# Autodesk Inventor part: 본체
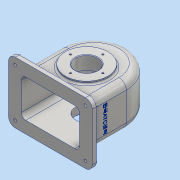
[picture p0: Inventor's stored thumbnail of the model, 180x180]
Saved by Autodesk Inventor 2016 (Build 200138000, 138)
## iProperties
Created: 2018-11
Part Number: 본체
Material: 알루미늄 6061
Document SubType Name: Modeling
Designer: 공506_39
Density: 2.7 g/cm^3
Appearance: 알루미늄 - 평지
Mass: 1092.08 g
Surface Area: 1182.21 cm^2
Volume: 404.475 cm^3
Author: 공506_39
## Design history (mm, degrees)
sketch "스케치2"
  geometry: L1 (-58, 0)-(58, 0); L2 (58, 0)-(58, -78); L3 (58, -78)-(-58, -78); L4 (-58, -78)-(-58, 0); A1 r 58 centre (0, 0) between (58, 0) and (-58, 0); 1 further point
  constraints: 8 end point, 2 parallel, 2 point on circle, 2 tangent, 1 centre point, 1 coincident, 1 horizontal, 1 perpendicular
  dimensions: "d0" = 116 diameter of A1; "d1" = 78 distance between parallel lines of L1 L3
extrude "돌출1" new body sketch "스케치2" distance "d2" = 77; taper "d3" = 0 deg
fillet "모깎기1" dims "d4" = 13
sketch "스케치3"
  geometry: L1 (103, -13)-(103, -64) reference; L2 (90, 0)-(0, 0) reference; L3 (-13, -13)-(-13, -64) reference; L4 (90, -77)-(0, -77) reference; L5 (-30, 16.5)-(120, 16.5); L6 (120, 16.5)-(120, -93.5); L7 (120, -93.5)-(-30, -93.5); L8 (-30, -93.5)-(-30, 16.5); L9 (-30, 16.5)-(120, -93.5); L10 (120, 16.5)-(-30, -93.5); A1 r 13 centre (90, -64) between (90, -77) and (103, -64) reference; A2 r 13 centre (90, -13) between (103, -13) and (90, 0) reference; A3 r 13 centre (0, -13) between (0, 0) and (-13, -13) reference; A4 r 13 centre (0, -64) between (-13, -64) and (0, -77) reference; 6 further points
  constraints: 12 end point, 6 midpoint, 2 parallel, 1 horizontal, 1 horizontal alignment, 1 perpendicular, 1 vertical alignment
  dimensions: "d6" = 110 distance of L5.end L6.end; "d7" = 150 distance of L6.end L7.end
extrude "돌출2" join sketch "스케치3" distance "d8" = 10; taper "d9" = 0 deg
fillet "모깎기2" dims "d10" = 12
node "작업 평면1"
sketch "스케치4"
  geometry: L1 (5, -80.5)-(121, -80.5) reference; L2 (5, -29.5)-(5, -80.5) reference; L3 (121, -29.5)-(5, -29.5) reference; L4 (121, -29.5)-(121, -80.5) reference; L5 (0, 0)-(126, 0) reference; L6 (138, -12)-(138, -98) reference; C1 r 6 at (63, -55); 1 further point
  constraints: 1 centre point
  dimensions: "d12" = 55 distance from line of L5 C1.centre; "d13" = 75 distance from line of L6 C1.centre; "d14" = 12 diameter of C1
extrude "돌출3" join sketch "스케치4" stored distance "d15" = 10; taper "d16" = 5 deg
sketch "스케치5"
  geometry: L1 (-63, -78)-(63, -78) reference; C1 r 38 at (0, -13); 1 further point
  constraints: 1 centre point, 1 vertical alignment
  dimensions: "d17" = 76 diameter of C1; "d18" = 65 distance from line of L1 C1.centre
extrude "돌출4" join sketch "스케치5" distance "d19" = 5; taper "d20" = 0 deg
node "작업 평면2"
node "작업 평면3"
sketch "스케치11"
  geometry: L1 (108, 93.5)-(-18, 93.5) reference; L2 (-30, 81.5)-(-30, -4.5) reference; L3 (-18, -16.5)-(108, -16.5) reference; L4 (120, -4.5)-(120, 81.5) reference; L5 (103, 13)-(103, 64) reference; L6 (0, 0)-(90, 0) reference; L7 (-13, 64)-(-13, 13) reference; L8 (90, 77)-(0, 77) reference; A1 r 12 centre (108, 81.5) between (120, 81.5) and (108, 93.5) reference; A2 r 12 centre (-18, 81.5) between (-18, 93.5) and (-30, 81.5) reference; A3 r 12 centre (-18, -4.5) between (-30, -4.5) and (-18, -16.5) reference; A4 r 12 centre (108, -4.5) between (108, -16.5) and (120, -4.5) reference; A5 r 13 centre (90, 13) between (90, 0) and (103, 13) reference; A6 r 13 centre (0, 13) between (-13, 13) and (0, 0) reference; A7 r 13 centre (0, 64) between (0, 77) and (-13, 64) reference; A8 r 13 centre (90, 64) between (103, 64) and (90, 77) reference; 5 further points
  constraints: 4 coincident
hole "구멍1" sketch "스케치11" at (-18, -4.5), (-18, 81.5), (108, 81.5), (108, -4.5) diameter "d35" = 5; stored, may be unused: countersink angle "d39" = 90 deg, drill point angle "d41" = 118 deg; dims "d36" = 6, "d37" = 12, "d38" = 4, "d40" = 8
node "작업 평면4"
hole "구멍4" diameter "d66" = 4.459; stored, may be unused: countersink angle "d70" = 90 deg, drill point angle "d72" = 118 deg; dims "d64" = 10, "d65" = 10, "d67" = 20, "d68" = 12, "d69" = 4, "d71" = 12.8
fillet "모깎기3" dims "d73" = 3
node "작업 평면5"
sketch "스케치16"
  geometry: L1 (58, 0)-(58, -65) reference; L2 (-58, -65)-(-58, 0) reference; L3 (0, 0)-(0, -121); L4 (-52, 0)-(-52, -121); L5 (52, -121)-(52, 0); A1 r 58 centre (0, 0) between (58, 0) and (-58, 0) reference; A2 r 52 centre (0, 0) between (52, 0) and (-52, 0); A3 r 52 centre (0, -121) between (-52, -121) and (52, -121); 2 further points
  constraints: 8 end point, 4 point on circle, 4 tangent, 2 centre point, 1 midpoint, 1 parallel, 1 vertical
  dimensions: "d74" = 6 radial gap between concentric circles of A1 A2; "d75" = 121 distance of L3.start L3.end
extrude "돌출8" cut sketch "스케치16" stored distance "d76" = 67; taper "d77" = 0 deg
node "작업 평면6"
sketch "스케치17"
  geometry: C1 r 38 at (0, 0) reference; C2 r 28 at (0, 0); 1 further point
  constraints: 1 centre point, 1 coincident
  dimensions: "d79" = 56 diameter of C2
extrude "돌출9" join sketch "스케치17" stored distance "d80" = 67; taper "d81" = 40 deg
sketch "스케치19"
  geometry: L1 (0, 0)-(0, 29); C1 r 38 at (0, 0) reference; 2 further points
  constraints: 2 end point, 1 coincident, 1 point on line, 1 vertical
  dimensions: "d82" = 29 distance of L1.start L1.end
hole "구멍5" sketch "스케치19" at (0, 29) diameter "d83" = 3.242; stored, may be unused: countersink angle "d87" = 90 deg, drill point angle "d89" = 118 deg; dims "d84" = 8, "d85" = 12, "d86" = 4, "d88" = 10
sketch "스케치20"
  geometry: C1 r 38 at (0, -13) reference; C2 r 38 at (0, -13); 1 further point
  constraints: 1 centre point, 1 coincident
  dimensions: "d94" = 76 diameter of C2
extrude "돌출10" join sketch "스케치20" stored distance "d95" = 67; taper "d96" = 0 deg
sketch "스케치21"
  geometry: L1 (0, 0)-(0, 29); C1 r 38 at (0, 0) reference; 2 further points
  constraints: 2 end point, 1 coincident, 1 vertical
  dimensions: "d97" = 29 distance of L1.start L1.end
hole "구멍6" sketch "스케치21" at (0, 29) diameter "d98" = 3.242; stored, may be unused: countersink angle "d102" = 90 deg, drill point angle "d104" = 118 deg; dims "d99" = 8, "d100" = 12, "d101" = 4, "d103" = 10
sketch "스케치22"
  geometry: C1 r 1.621 at (29, 0) reference; C2 r 1.621 at (0, -29) reference; C3 r 1.621 at (-29, 0) reference; C4 r 1.621 at (0, 29) reference; C5 r 38 at (0, 0) reference; 2 further points
  constraints: 1 coincident
hole "구멍7" sketch "스케치22" at (0, 0) diameter "d108" = 40; stored, may be unused: countersink angle "d112" = 90 deg, drill point angle "d114" = 118 deg; dims "d109" = 8, "d110" = 12, "d111" = 4, "d113" = 10
chamfer "모따기2" distance "d115" = 1; stored, may be unused: second distance "d116" = 2, angle "d117" = 45 deg
fillet "모깎기4" dims "d118" = 3
fillet "모깎기5" dims "d119" = 8
fillet "모깎기6" dims "d120" = 3
sketch "스케치23"
  geometry: L1 (-17.5, -78)-(68.5, -78) reference; L2 (80.5, -78)-(80.5, -71) reference; L3 (-29.5, -71)-(-29.5, -78) reference; L4 (-13, 0)-(-13, -65) reference; 2 further points
  constraints: 1 coincident, 1 other
  dimensions: "d123" = 40 distance from line of L1 point (25.5, -38); "d125" = 38.5 distance from line of point (25.5, -38) L4
feature "엠보싱1" sketch "스케치23" dims "d126" = 0.5, "d127" = 0
node "솔리드1"
pattern_circular "원형 패턴3" dims angle "d91" = 360 deg
pattern_circular "원형 패턴4" dims angle "d106" = 360 deg
node "투영된 루프1"
node "투영된 루프2"
node "투영된 루프6"
node "투영된 루프9"
node "투영된 루프10"
node "투영된 루프11"
other parameters: "d11" = -142, "d21" = -24, "d25" = -87, "d78" = -24
